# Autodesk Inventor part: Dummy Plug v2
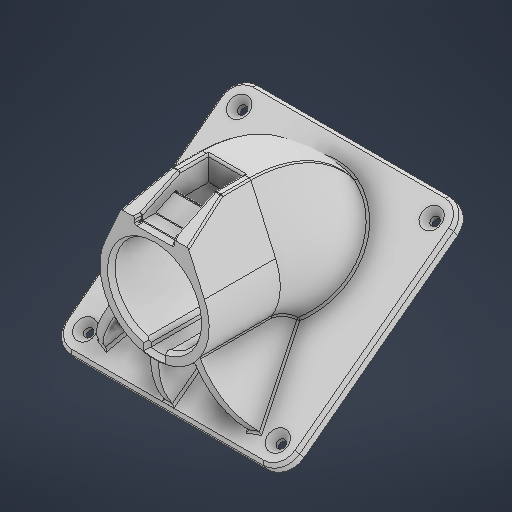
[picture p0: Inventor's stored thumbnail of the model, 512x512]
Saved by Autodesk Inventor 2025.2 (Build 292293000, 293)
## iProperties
Created: 2025-01
Part Number: Dummy Plug v2
Material: Generic
Document SubType Name: Modeling
Designer: austi
Density: 1 g/cm^3
Appearance: Default
Author: austi
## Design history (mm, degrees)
sketch "Receiver Outline"
  geometry: L1 (4.25, -21.713)-(4.25, -25.27); L2 (-4.25, -25.27)-(-4.25, -21.713); L3 (-12.3, 24.176)-(12.3, 24.176); L4 (12.3, 24.176)-(12.3, 39.125); L5 (12.3, 39.125)-(-12.3, 39.125); L6 (-12.3, 39.125)-(-12.3, 24.176); L7 (12.3, 39.125)-(24.789, 11.012); L8 (-12.3, 39.125)-(-24.789, 11.012); A1 r 27.125 centre (0, 0) between (-12.3, 24.176) and (0, -27.125); A2 r 22.125 centre (0, 0) between (4.25, -21.713) and (0, -22.125); A3 r 25.625 centre (0, 0) between (-4.25, -25.27) and (4.25, -25.27); 5 further points
  constraints: 16 end point, 10 point on circle, 3 centre point, 3 coincident, 3 parallel, 2 tangent, 1 horizontal, 1 perpendicular
  dimensions: "d0" = 4.25 distance from line of point (0, 0) L1 (= d2); "d1" = 8.5 distance between parallel lines of L2 L1; "d2" = 4.25 distance from line of point (0, 0) L2 (derived); "d3" = 12.3 distance from line of point (0, 0) L6 (= d5); "d4" = 24.6 distance between parallel lines of L4 L6; "d5" = 12.3 distance from line of point (0, 0) L4 (derived); "d6" = 44.25 diameter of A2; "d9" = 3.5 distance of point (0, -25.625) A2.end; "d10" = 1.5 distance of A1.end point (0, -25.625); "d11" = 17 distance from line of L5 point (0, 22.125)
node "Receiver Depth Offset"
node "Pivot Plane"
extrude "Receiver Body" join sketch "Receiver Outline" stored distance "d23" = 10; taper "d24" = 0 deg
sketch "Sketch20"
  geometry: L1 (4.25, -25.27)-(4.25, -21.713) reference; L2 (-4.25, -21.713)-(-4.25, -25.27) reference; L3 (-24.789, 11.012)-(-12.3, 39.125) reference; L4 (-12.3, 39.125)-(12.3, 39.125) reference; L5 (12.3, 39.125)-(24.789, 11.012) reference; L6 (0, -27.125)-(10.277, -27.125); A1 r 27.125 centre (0, 0) between (-24.789, 11.012) and (24.789, 11.012) reference; A2 r 25.625 centre (0, 0) between (-4.25, -25.27) and (4.25, -25.27) reference; A3 r 22.125 centre (0, 0) between (4.25, -21.713) and (-4.25, -21.713) reference; A4 r 27.125 centre (0, 0) between (-24.789, 11.012) and (24.789, 11.012) reference; A5 r 27.125 centre (0, 0) between (-24.789, 11.012) and (24.789, 11.012) reference; 1 further point
  constraints: 2 end point, 1 horizontal, 1 point on circle, 1 tangent
  node "Project Cut Edges7"
sketch "Sketch12"
  geometry: L1 (24.6, 35.4)-(24.6, 0) reference; L2 (24.6, 0)-(0, 0) reference; L3 (0, 0)-(0, 35.4) reference; L4 (0, 35.4)-(24.6, 35.4) reference; L5 (0, 35.4)-(24.6, 35.4) reference; L6 (3.75, 0)-(20.85, 0); L7 (20.85, 0)-(20.85, 35.4); L8 (20.85, 35.4)-(3.75, 35.4); L9 (3.75, 35.4)-(3.75, 0); 5 further points
  constraints: 8 end point, 2 midpoint, 2 parallel, 2 point on line, 1 horizontal, 1 perpendicular
  dimensions: "d54" = 17.1 distance between parallel lines of L7 L9
  node "Project Cut Edges3"
workpoint "Work Point14"
workplane "Work Plane37"
  workplane "Work Plane36"
extrude "Extrusion9" cut sketch "Sketch12" distance "d101" = 7.5; taper "d102" = 0 deg
workplane "Work Plane21"
  workplane "Work Plane19"
sketch "Sketch22" dims "d93" = 66.5
  geometry: 4 further points
  constraints: 1 vertical alignment, 2 other
  dimensions: "d94" = 1 distance of point (0, 1) point (0, 0)
workplane "Work Plane22"
sketch "Sketch23"
  geometry: L1 (23.401, 21.006)-(34.494, -21.405) reference; L2 (20.627, 26.078)-(-20.627, -26.078) reference; L3 (-56.456, -71.376)-(69.49, 87.853) reference; A1 r 28.377 centre (21.715, 27.454) between (4.111, 5.197) and (28.895, 0); 6 further points
  constraints: 2 line through centre, 2 point on circle, 1 centre point, 1 point on line
loft "Loft3" sketch "Sketch23" dims "d95" = 0, "d96" = 90 deg, "d97" = 0, "d98" = 90 deg, "d99" = 0, "d100" = 90 deg
  node "Edges3"
sketch "Sketch24"
  geometry: L1 (47.886, -43.25)-(-47.886, -43.25); L2 (-57.886, -33.25)-(-57.886, 62.522); L3 (-47.886, 72.522)-(47.886, 72.522); L4 (57.886, 62.522)-(57.886, -33.25); C1 r 2.075 at (47.886, -33.25); C2 r 2.075 at (-47.886, -33.25); C3 r 2.075 at (-47.886, 62.522); C4 r 2.075 at (47.886, 62.522); A1 r 33.25 centre (0, 0) between (-11.555, -31.178) and (11.555, -31.178) reference; A2 r 33.25 centre (0, 0) between (11.555, -31.178) and (-11.555, -31.178) reference; A3 r 10 centre (47.886, -33.25) between (47.886, -43.25) and (57.886, -33.25); A4 r 10 centre (-47.886, -33.25) between (-57.886, -33.25) and (-47.886, -43.25); A5 r 10 centre (-47.886, 62.522) between (-47.886, 72.522) and (-57.886, 62.522); A6 r 10 centre (47.886, 62.522) between (57.886, 62.522) and (47.886, 72.522); 7 further points; 1 other entity
  constraints: 9 point on circle, 8 centre point, 8 end point, 8 tangent, 4 coincident, 3 equal radius, 2 parallel, 2 vertical alignment, 1 horizontal, 1 midpoint, 1 perpendicular, 2 other
  dimensions: "d103" = 10 distance from line of point (0, -33.25) L1; "d105" = 10 distance from line of point (0, 62.522) L3; "d107" = 115.7717 distance between parallel lines of L3 L1 (derived); "d108" = 115.7717 distance between parallel lines of L4 L2 (= d107); "d109" = 10 radius of A3; "d110" = 4.15 diameter of C1; "d111" = 4.15 diameter of C4 (= d110); "d112" = 4.15 diameter of C2 (= d110); "d113" = 4.15 diameter of C3 (= d110)
extrude "Extrusion10" join sketch "Sketch24" distance "d114" = 5; taper "d115" = 0 deg
workpoint "Work Point11"
workplane "Work Plane30"
  workpoint "Work Point12"
sketch "Sketch30"
  geometry: L1 (35.4, -66.25)-(35.4, -58.75) reference; L2 (0, -58.75)-(0, -49.25) reference; L3 (0, -49.25)-(35.4, -49.25) reference; L4 (35.4, -49.25)-(35.4, -1.5) reference; L5 (35.4, -1.5)-(0, -1.5) reference; L6 (0, -1.5)-(0, 0) reference; L7 (0, 0)-(35.4, 0) reference; L8 (36.8, 0.197)-(5.437, 23.831) reference; L9 (5.437, 23.831)-(8.446, 27.824) reference; L10 (8.446, 27.824)-(100.905, -41.849) reference; L11 (100.905, -41.849)-(97.896, -45.842) reference; L12 (97.896, -45.842)-(89.91, -39.824) reference; L13 (-23.804, 0)-(121.708, 0) reference; L14 (35.4, -58.75)-(0, -58.75) reference; A1 r 37.062 centre (37.062, 0) between (7.463, 22.304) and (0, 0); 1 further point
  constraints: 2 line through centre, 2 point on circle, 1 centre point, 1 point on line, 2 other
  dimensions: "d126" = 37.06164 radius of A1 (derived)
  node "Project Cut Edges12"
sketch "Sketch31"
  geometry: L1 (-1.987, -32.923)-(2.013, -32.923); L2 (2.013, -32.923)-(2.013, -69.985); L3 (2.013, -69.985)-(-1.987, -69.985); L4 (-1.987, -69.985)-(-1.987, -32.923); 4 further points
  constraints: 8 end point, 2 parallel, 1 coincident, 1 horizontal, 1 midpoint, 1 perpendicular
  dimensions: "d127" = 4 distance between parallel lines of L4 L2
revolve "Revolution3" sketch "Sketch31" stored, may be unused: angle "d128" = 360 deg
workaxis "Work Axis8"
workplane "Work Plane33"
  workplane "Work Plane32"
sketch "Sketch32"
  geometry: L1 (35.4, -34.507)-(35.4, -30.734) reference; L2 (0, -30.734)-(0, -19.736) reference; L3 (0, -19.736)-(35.4, -19.736) reference; L4 (35.4, -19.736)-(35.4, 19.736) reference; L5 (35.4, 19.736)-(0, 19.736) reference; L6 (0, 19.736)-(0, 25.214) reference; L7 (0, 25.214)-(35.4, 25.214) reference; L8 (44.807, 30.321)-(5.423, 64.565) reference; L9 (5.423, 64.565)-(8.432, 69.174) reference; L10 (8.432, 69.174)-(100.904, -11.232) reference; L11 (100.904, -11.232)-(97.896, -15.84) reference; L12 (97.896, -15.84)-(89.684, -8.7) reference; L13 (35.4, -39.388)-(0, -39.388) reference; L14 (0, -39.388)-(0, -34.507) reference; L15 (0, -34.507)-(35.4, -34.507) reference; L16 (0, 25.214)-(50.68, 25.214); L17 (50.68, 25.214)-(5.423, 64.565); L18 (35.4, -30.734)-(0, -30.734) reference; A1 r 50.68 centre (50.68, 25.214) between (12.435, 58.468) and (0, 25.214); 1 further point
  constraints: 4 end point, 2 line through centre, 2 point on circle, 2 point on line, 1 centre point, 1 collinear, 2 other
  node "Project Cut Edges13"
workplane "Work Plane35"
  workaxis "Work Axis9"
  workplane "Work Plane34"
sketch "Sketch33"
  geometry: L1 (0, -50.68)-(0, -47.312) reference; L2 (-2, -50.68)-(2, -50.68); L3 (2, -50.68)-(2, 0); L4 (2, 0)-(-2, 0); L5 (-2, 0)-(-2, -50.68); L6 (-93.206, 0)-(117.746, 0) reference; 5 further points
  constraints: 8 end point, 2 coincident, 2 midpoint, 2 parallel, 1 horizontal, 1 perpendicular
  dimensions: "d134" = 4 distance between parallel lines of L5 L3
revolve "Revolution4" sketch "Sketch33" stored, may be unused: angle "d135" = 360 deg
sketch "Sketch34"
  geometry: L1 (-38.398, 4.371)-(-38.377, 4.475) reference; L2 (-38.377, 4.475)-(-40.154, 2.217) reference; L3 (-40.154, 2.217)-(-50.163, 5.443) reference; L4 (-50.163, 5.443)-(27.798, 104.468) reference; L5 (27.798, 104.468)-(37.806, 101.241) reference; L6 (37.806, 101.241)-(14.799, 72.018) reference; L7 (0, 43.225)-(0, 0) reference; L8 (0, 0)-(-4, 0) reference; L9 (-4, 0)-(-4, 41.11) reference; L10 (-11.163, 39.041)-(-32.115, 12.428) reference; L11 (-32.115, 12.428)-(-34.057, 3.04) reference; L12 (98.559, 50.68)-(-121.947, 50.68) reference; 2 further points; 1 other entity
  constraints: 4 other
revolve "Revolution5" sketch "Sketch34" stored, may be unused: angle "d136" = 360 deg
workplane "Work Plane39"
sketch "Sketch35"
  geometry: L1 (32.248, -39.982)-(19.864, -18.471) reference; L2 (1.994, -27.052)-(1.991, -39.982) reference; L3 (1.991, -39.982)-(32.248, -39.982) reference; L4 (-8.55, 39.125)-(-8.55, 31.625) reference; L5 (8.55, 31.625)-(8.55, 39.125) reference; L6 (8.55, 39.125)-(12.3, 39.125) reference; L7 (12.3, 39.125)-(24.789, 11.012) reference; L8 (22.537, -15.095)-(36.864, -39.982) reference; L9 (36.864, -39.982)-(57.864, -39.982) reference; L10 (57.864, -39.982)-(57.862, -46.243) reference; L11 (57.862, -46.243)-(-57.91, -46.243) reference; L12 (-57.91, -46.243)-(-57.908, -39.982) reference; L13 (-57.908, -39.982)-(-2.009, -39.982) reference; L14 (-2.009, -39.982)-(-2.006, -27.051) reference; L15 (-24.789, 11.012)-(-12.3, 39.125) reference; L16 (-12.3, 39.125)-(-8.55, 39.125) reference; L17 (4.25, -25.27)-(4.25, -21.713) reference; L18 (-4.25, -21.713)-(-4.25, -25.27) reference; L19 (-8.55, 39.125)-(8.55, 39.125); L20 (8.55, 39.125)-(8.55, 27.125); L21 (8.55, 27.125)-(-8.55, 27.125); L22 (-8.55, 27.125)-(-8.55, 39.125); L23 (-8.55, 31.625)-(8.55, 31.625) reference; A1 r 27.125 centre (0, 0) between (1.994, -27.052) and (19.864, -18.471) reference; A2 r 27.125 centre (0, 0) between (22.537, -15.095) and (24.789, 11.012) reference; A3 r 25.625 centre (0, 0) between (-4.25, -25.27) and (4.25, -25.27) reference; A4 r 22.125 centre (0, 0) between (4.25, -21.713) and (-4.25, -21.713) reference; A5 r 27.125 centre (0, 0) between (-24.789, 11.012) and (-2.006, -27.051) reference; 5 further points
  constraints: 8 end point, 2 parallel, 1 collinear, 1 horizontal, 1 perpendicular, 1 point on circle
  dimensions: "d140" = 5 distance from line of point (0, 22.125) L21
extrude "Extrusion12" cut sketch "Sketch35" stored distance "d141" = 10; taper "d142" = 0 deg
chamfer "Chamfer7" distance "d147" = 1.25; stored, may be unused: second distance "d148" = 2.5, angle "d149" = 20 deg
fillet "Fillet4" dims "d150" = 2
workplane "Work Plane41"
  workplane "Work Plane40"
sketch "Sketch36"
  geometry: L1 (44.86, 30.344)-(5.45, 64.66) reference; L2 (5.45, 64.66)-(8.46, 69.273) reference; L3 (8.46, 69.273)-(100.906, -11.225) reference; L4 (100.906, -11.225)-(97.896, -15.838) reference; L5 (97.896, -15.838)-(89.687, -8.69) reference; L6 (35.4, -39.42)-(0, -39.42) reference; L7 (0, -39.42)-(0, -36.829) reference; L8 (0, -36.829)-(2.5, -34.334) reference; L9 (2.5, -34.334)-(35.4, -34.334) reference; L10 (35.4, -34.334)-(35.4, -25.554) reference; L11 (35.4, -25.554)-(20, -25.554) reference; L12 (20, -25.554)-(20, -30.754) reference; L13 (0, -30.754)-(0, -21.128) reference; L14 (2.5, -19.736)-(35.4, -19.736) reference; L15 (35.4, -19.736)-(35.4, 19.736) reference; L16 (35.4, 19.736)-(2.5, 19.736) reference; L17 (0, 21.128)-(0, 25.214) reference; L18 (0, 25.214)-(35.4, 25.214) reference; L19 (0, 25.214)-(50.75, 25.214); L20 (50.75, 25.214)-(5.45, 64.66); L21 (20, -30.754)-(0, -30.754) reference; A1 r 50.75 centre (50.75, 25.214) between (12.476, 58.542) and (0, 25.214); 1 further point
  constraints: 4 end point, 2 line through centre, 2 point on circle, 2 point on line, 1 centre point, 1 collinear, 4 other
  node "Project Cut Edges16"
workplane "Work Plane43"
  workaxis "Work Axis10"
  workplane "Work Plane42"
sketch "Sketch37"
  geometry: L1 (0, -50.75)-(0, -47.364) reference; L2 (-119.974, 0)-(100.449, 0) reference; L3 (2, 0)-(-2, 0); L4 (-2, 0)-(-2, -50.75); L5 (-2, -50.75)-(2, -50.75); L6 (2, -50.75)-(2, 0); L7 (-36.329, -46.383)-(-38.03, -48.554) reference; L8 (-38.03, -48.554)-(-48.002, -45.333) reference; L9 (-48.002, -45.333)-(29.608, 53.753) reference; L10 (29.608, 53.753)-(39.579, 50.532) reference; L11 (39.579, 50.532)-(16.763, 21.402) reference; L12 (-9.147, -11.678)-(-30.327, -38.719) reference; L13 (-30.327, -38.719)-(-32.182, -47.661) reference; L14 (2, -4)-(-2, -4); 6 further points; 1 other entity
  constraints: 10 end point, 3 point on line, 2 midpoint, 2 parallel, 2 perpendicular, 1 horizontal, 2 other
  dimensions: "d156" = 4 distance between parallel lines of L4 L6; "d158" = 4 distance between parallel lines of L3 L14
revolve "Revolution6" sketch "Sketch37" stored, may be unused: angle "d157" = 30.61 deg
sketch "Sketch38"
  geometry: L1 (40.03, 2.196)-(38.329, 4.368) reference; L2 (34.182, 3.09)-(32.327, 12.031) reference; L3 (32.327, 12.031)-(11.147, 39.072) reference; L4 (0, 0)-(0, 43.266) reference; L5 (4, 0)-(0, 0) reference; L6 (4, 41.147)-(4, 0) reference; L7 (50.002, 5.417)-(40.03, 2.196) reference; L8 (-27.608, 104.504)-(50.002, 5.417) reference; L9 (-37.579, 101.283)-(-27.608, 104.504) reference; L10 (-14.763, 72.153)-(-37.579, 101.283) reference; L11 (121.974, 50.75)-(-98.449, 50.75) reference; 2 further points; 1 other entity
  constraints: 4 other
revolve "Revolution7" sketch "Sketch38" stored, may be unused: angle "d159" = 360 deg
fillet "Fillet6" dims "d160" = 1
chamfer "Chamfer8" distance "d161" = 1; stored, may be unused: second distance "d162" = 2.5, angle "d163" = 20 deg
chamfer "Chamfer9" distance "d164" = 2.875; stored, may be unused: second distance "d165" = 2.5, angle "d166" = 20 deg
chamfer "Chamfer10" distance "d167" = 1.5; stored, may be unused: second distance "d168" = 2.5, angle "d169" = 20 deg
sketch "Sketch39"
  geometry: L1 (27.932, 35.4)-(27.932, 0) reference; L2 (27.932, 0)-(22.1, 0) reference; L3 (22.1, 0)-(2.5, 0) reference; L4 (3.75, 2.5)-(2.5, 0) reference; L5 (3.75, 20)-(3.75, 2.5) reference; L6 (3.75, 35.4)-(3.75, 20) reference; L7 (20.85, 35.4)-(3.75, 35.4) reference; L8 (20.85, 20)-(20.85, 35.4) reference; L9 (3.75, 20)-(20.85, 20) reference; L10 (-3.332, 0)-(-3.332, 35.4) reference; L11 (2.5, 0)-(-3.332, 0) reference; L12 (22.1, 0)-(20.85, 2.5) reference; L13 (20.85, 2.5)-(20.85, 20) reference; L14 (20.85, 20)-(3.75, 20) reference; L15 (3.75, 2.5)-(3.75, 20) reference; L16 (2.5, 0)-(3.75, 2.5) reference; L17 (22.1, 0)-(2.5, 0) reference; L18 (20.85, 2.5)-(22.1, 0) reference; L19 (20.85, 20)-(20.85, 2.5) reference; L20 (3.75, 9)-(20.85, 9); 7 further points
  constraints: 2 end point, 2 point on line, 1 perpendicular, 5 other
  dimensions: "d170" = 9 distance between parallel lines of L17 L20
extrude "Extrusion13" cut sketch "Sketch39" stored distance "d171" = 7; taper "d172" = 0 deg
workplane "Work Plane44"
sketch "Sketch40"
  geometry: L1 (11, 0)-(0, 0) reference; L2 (0, 0)-(11, 0) reference; L3 (0, 0)-(0, 4.5) reference; L4 (0, 0)-(0, 4.5) reference; L5 (11, 4.5)-(11, 0) reference; L6 (11, 0)-(11, 4.5) reference; L7 (-6.5, 4.5)-(-9, 4.5) reference; L8 (-9, 4.5)-(-6.5, 4.5) reference; L9 (-6.5, 4.5)-(0, 4.5) reference; L10 (0, 4.5)-(-6.5, 4.5) reference; L11 (11, 4.5)-(26.4, 4.5) reference; L12 (11, 4.5)-(26.4, 4.5) reference; L13 (9.5, 0)-(0, 4.5); 4 further points
  constraints: 2 end point, 1 point on line
  dimensions: "d173" = 1.5 distance from line of L5 L13.start
extrude "Extrusion14" cut sketch "Sketch40" stored distance "d174" = 10; taper "d175" = 0 deg
chamfer "Chamfer11" distance "d176" = 1.25; stored, may be unused: second distance "d177" = 2.5, angle "d178" = 45 deg
fillet "Fillet7" dims "d179" = 1
workplane "Work Plane45"
sketch "Sketch41"
  geometry: L1 (18.297, 31.529)-(9.203, 27.221) reference; L2 (18.297, 31.529)-(9.203, 27.221) reference; L3 (0, 39.125)-(2.736, 39.125) reference; L4 (35.4, 39.125)-(0, 39.125) reference; L5 (2.736, 39.125)-(35.4, 39.125) reference; L6 (0, -26.306)-(0, -26.306) reference; L7 (0, -22.719)-(0, -26.306) reference; L8 (0, -22.719)-(0, -22.719) reference; L9 (0, -26.306)-(0, -22.719) reference; L10 (0, 39.125)-(0, 38.125) reference; L11 (0, 38.531)-(0, 39.125) reference; L12 (0, 38.531)-(0, 11.012) reference; L13 (0, 11.012)-(0, -16.81) reference; L14 (0, -16.81)-(0, -27.125) reference; L15 (0, -27.125)-(0, -26.906) reference; L16 (0, -27.345)-(0, -26.906) reference; L17 (0, -27.356)-(0, -27.345) reference; L18 (0, -26.972)-(0, -27.356) reference; L19 (0, -26.972)-(0, -16.863) reference; L20 (0, -16.863)-(0, 11.012) reference; L21 (0, 11.012)-(0, 38.531) reference; L22 (0, 39.125)-(0, 38.531) reference; L23 (0, 38.125)-(0, 39.125) reference; L24 (0, 38.125)-(0, 26.769) reference; L25 (0, 25.875)-(0, 26.769) reference; L26 (0, 26.769)-(0, 25.875) reference; L27 (0, 26.769)-(0, 38.125) reference; L28 (2.736, 27.125)-(2.504, 27.125) reference; L29 (2.504, 27.125)-(2.736, 27.125) reference; L30 (2.504, 27.125)-(8.775, 27.125) reference; L31 (8.775, 27.125)-(2.504, 27.125) reference; L32 (20, 27.125)-(35.4, 27.125) reference; L33 (20, 27.125)-(35.4, 27.125) reference; L34 (20, 27.125)-(20, 30.625) reference; L35 (20, 30.625)-(20, 27.125) reference; L36 (0, 29.125)-(21.111, 39.125); 6 further points
  constraints: 2 end point, 2 point on line, 1 parallel
  dimensions: "d180" = 10 distance of L3.start L36.start
extrude "Extrusion15" cut sketch "Sketch41" extent not by distance; stored distance "d181" = 0; taper "d182" = 0 deg
fillet "Fillet8" dims "d183" = 1
feature "ގ耀ސ耀ޒ耀ޔ耀ޖ耀ޘ耀ޚ耀ޜ耀" dims "d0" = 4.25 (= d2), "d1" = 8.5, "d2" = 4.25 (derived), "d3" = 12.3 (= d5), "d4" = 24.6, "d5" = 12.3 (derived), "d6" = 44.25, "d9" = 3.5, "d10" = 1.5, "d11" = 17, "d12" = -35.4, "d23" = 10, "d24" = 0, "d54" = 17.1, "d90" = 53 deg, "d92" = 1, "d93" = 66.5, "d94" = 1, "d95" = 0, "d96" = 90 deg, "d97" = 0, "d98" = 90 deg, "d99" = 0, "d100" = 90 deg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
body "Solid1"
node "Projected Loop11"
workaxis "Work Axis6"
workpoint "Work Point13"
node "Projected Loop15"
node "Projected Loop16"
node "Projected Loop17"
node "Projected Loop18"
node "Projected Loop19"
node "Projected Loop20"
node "Projected Loop21"
node "Projected Loop22"
node "Projected Loop23"
node "Projected Loop24"
node "Projected Loop25"
node "Projected Loop26"
node "Project Cut Edges14"
node "Project Cut Edges15"
node "Project Cut Edges17"
node "Project Cut Edges18"
node "Project Cut Edges19"
